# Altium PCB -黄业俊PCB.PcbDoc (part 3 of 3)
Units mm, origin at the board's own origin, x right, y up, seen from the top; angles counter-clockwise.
Board outline 130 x 100.6 mm, 2 copper layers (Top Layer, Bottom Layer); 47 components, 24 nets, 117 pads, 0 vias.
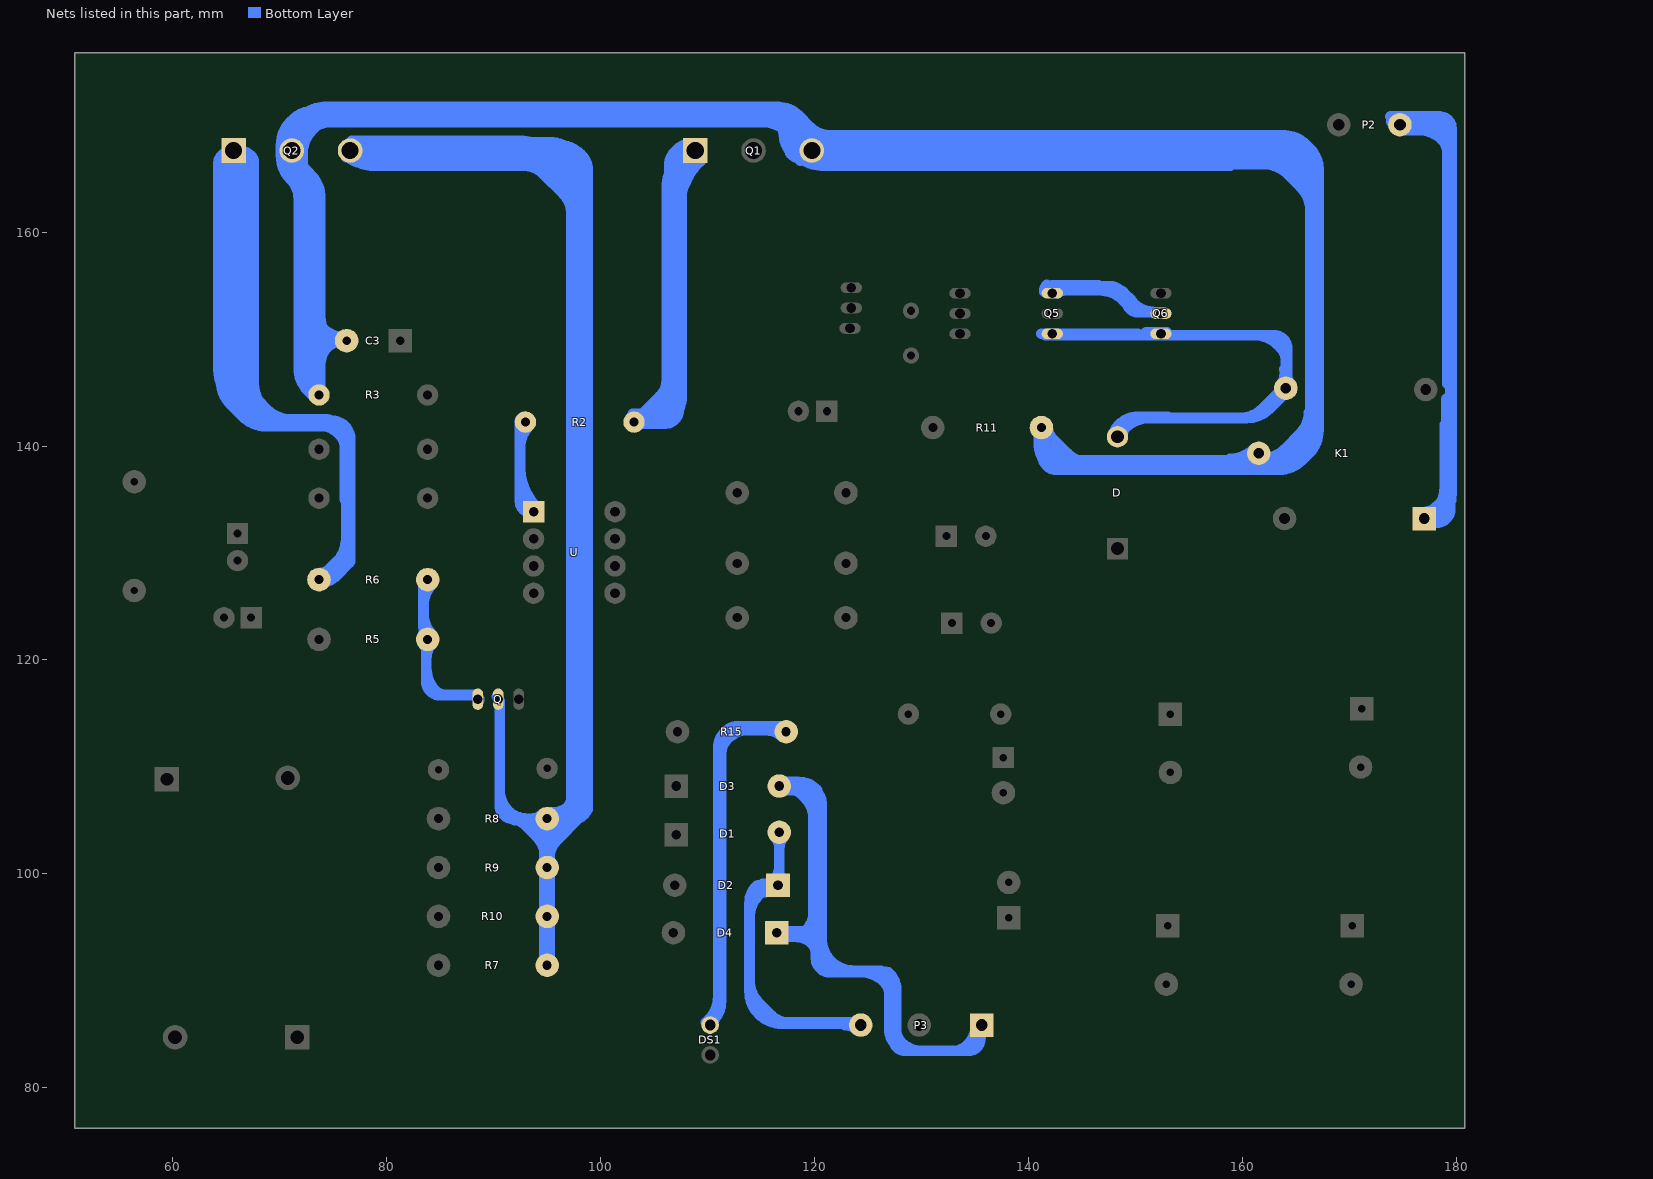
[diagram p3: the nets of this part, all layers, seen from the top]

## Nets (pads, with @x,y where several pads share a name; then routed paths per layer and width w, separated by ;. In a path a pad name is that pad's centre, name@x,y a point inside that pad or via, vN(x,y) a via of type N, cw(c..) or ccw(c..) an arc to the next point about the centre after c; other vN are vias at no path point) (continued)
NetD1_1: D1.1 D2.2 P3.3 | length 114.1
  Bottom Layer w1: 113.919,91.059 113.919,89.408 ccw(c116.985,89.408) 114.817,87.24 115.053,87.004 ccw(c117.221,89.172) 117.221,86.106 P3.3@123.698,86.106 ; 113.919,91.313 113.919,90.043 ccw(c116.985,90.043) 114.817,87.875 115.815,86.877 ccw(c117.983,89.045) 117.983,85.979 120.142,85.979 ; 113.919,94.107 113.919,95.885 cw(c116.985,95.885) 114.817,98.053 115.465,98.701 cw(c116.332,97.834) D2.2@116.332,99.06 ; 115.02,98.256 cw(c115.754,97.523) D2.2@116.281,98.416 ; 115.412,98.267 cw(c116.713,96.966) D2.2@116.713,98.806 ; D2.2@116.586,98.933 114.861,98.933 ccw(c114.861,98.499) 114.554,98.806 ccw(c116.087,97.273) 113.919,97.273 113.919,89.001 ccw(c116.923,89.001) 114.046,88.137 ccw(c116.923,89.001) 114.173,87.792 ccw(c116.923,89.001) 114.799,86.877 ccw(c116.967,89.045) 116.967,85.979 P3.3@124.587,85.979 ; D2.2@116.713,99.06 D1.1@116.713,103.886 ; 122.271,86.106 cw(c122.271,83.79) P3.3@123.909,85.428 ; 115.137,98.933 cw(c115.137,97.484) 116.162,98.509 ccw(c115.137,97.484) 115.137,98.933 ; 115.137,98.933 ccw(c115.137,100.382) D2.2@116.162,99.357 ; 115.137,98.933 ccw(c115.137,100.382) D2.2@116.162,99.357 ; 115.164,99.06 cw(c115.164,97.905) D2.2@116.1,98.582 ; 115.164,99.06 cw(c115.164,97.905) D2.2@116.1,98.582 ; 115.164,99.06 cw(c115.164,97.905) D2.2@116.1,98.582 ; 115.444,99.06 ccw(c115.444,100.075) D2.2@116.162,99.357 ; 115.444,99.06 ccw(c115.444,100.075) D2.2@116.162,99.357 ; 115.444,99.06 ccw(c115.444,100.075) D2.2@116.162,99.357 ; D2.2@116.162,99.357 ccw(c114.831,100.688) 116.713,100.688 ; D2.2@116.162,99.357 ccw(c114.831,100.688) 116.713,100.688 ; D2.2@116.162,99.357 ccw(c114.831,100.688) 116.713,100.688 ; D2.2@116.162,99.357 ccw(c114.831,100.688) 116.713,100.688 ; D2.2@116.162,99.357 ccw(c114.831,100.688) 116.713,100.688 ; D1.1@116.289,103.462 cw(c115.264,102.437) 116.713,102.437 ; D1.1@116.289,103.462 cw(c115.264,102.437) 116.713,102.437 ; D1.1@116.289,103.462 cw(c115.264,102.437) 116.713,102.437 ; D1.1@116.289,103.462 cw(c115.264,102.437) 116.713,102.437 ; D1.1@116.289,103.462 cw(c115.264,102.437) 116.713,102.437 ; 116.713,100.075 ccw(c117.728,100.075) D2.2@117.01,99.357 ; 116.713,100.075 ccw(c117.728,100.075) D2.2@117.01,99.357 ; 116.713,100.075 ccw(c117.728,100.075) D2.2@117.01,99.357 ; 116.713,100.075 ccw(c117.728,100.075) D2.2@117.01,99.357 ; 116.713,100.075 ccw(c117.728,100.075) D2.2@117.01,99.357 ; 116.713,102.437 cw(c118.162,102.437) D1.1@117.137,103.462 ; 116.713,102.437 cw(c118.162,102.437) D1.1@117.137,103.462 ; 116.713,102.437 cw(c118.162,102.437) D1.1@117.137,103.462 ; 116.713,102.437 cw(c118.162,102.437) D1.1@117.137,103.462 ; 116.713,102.437 cw(c118.162,102.437) D1.1@117.137,103.462 ; 122.578,85.979 cw(c122.578,84.097) P3.3@123.909,85.428 ; 122.578,85.979 cw(c122.578,84.097) P3.3@123.909,85.428 ; 122.578,85.979 cw(c122.578,84.097) P3.3@123.909,85.428 ; 122.578,85.979 cw(c122.578,84.097) P3.3@123.909,85.428 ; 122.578,85.979 cw(c122.578,84.097) P3.3@123.909,85.428 ; 122.884,85.852 ccw(c122.884,87.301) P3.3@123.909,86.276 ; 122.884,85.852 cw(c122.884,84.403) P3.3@123.909,85.428 ; 122.884,85.852 ccw(c122.884,87.301) P3.3@123.909,86.276 ; 122.884,85.852 cw(c122.884,84.403) P3.3@123.909,85.428 ; 122.884,85.852 ccw(c122.884,87.301) P3.3@123.909,86.276 ; 122.884,85.852 cw(c122.884,84.403) P3.3@123.909,85.428 ; 123.191,85.979 ccw(c123.191,86.994) P3.3@123.909,86.276 ; 123.191,85.979 ccw(c123.191,86.994) P3.3@123.909,86.276 ; 123.191,85.979 ccw(c123.191,86.994) P3.3@123.909,86.276 ; 123.191,85.979 ccw(c123.191,86.994) P3.3@123.909,86.276 ; 123.191,85.979 ccw(c123.191,86.994) P3.3@123.909,86.276
NetD3_1: D3.1 D4.2 P3.1 | length 235.5
  Bottom Layer w1: D4.2@116.205,94.615 118.999,94.615 cw(c118.999,93.345) 119.396,94.551 cw(c118.999,93.345) 120.142,93.899 ; D4.2@116.332,94.107 118.228,94.107 ; D3.1@116.713,108.331 118.662,108.331 cw(c118.662,106.597) 119.888,107.823 ; D4.2@116.84,94.488 ccw(c117.147,94.795) 117.147,94.361 118.526,94.361 ccw(c118.526,95.197) 119.117,94.606 ccw(c116.949,96.774) 120.015,96.774 120.015,106.767 ccw(c118.999,106.767) 119.717,107.486 ccw(c117.983,105.751) 117.983,108.204 cw(c117.983,109.43) 117.116,108.563 117.094,108.585 118.429,108.585 ; D4.2@116.968,94.806 ccw(c118.228,95.592) 118.228,94.107 ; D3.1@117.094,107.823 118.005,107.823 ; D3.1@117.23,107.9 cw(c118.429,107.193) 118.429,108.585 ; D3.1@117.291,108.365 ccw(c118.005,108.564) 118.005,107.823 ; 117.601,94.361 ccw(c117.601,93.346) 116.883,94.064 cw(c118.214,92.733) 118.214,94.615 ; 117.601,94.615 cw(c117.601,95.63) 116.883,94.912 ccw(c118.214,96.243) 118.214,94.361 ; 117.855,108.331 cw(c117.855,109.346) D3.1@117.137,108.628 ; 118.468,108.331 ccw(c118.468,106.449) D3.1@117.137,107.78 ; 119.126,108.458 cw(c119.126,107.538) 119.776,108.189 cw(c118.281,106.693) 120.396,106.693 120.396,93.586 ccw(c123.431,93.586) 121.285,91.44 ; 119.634,94.869 ccw(c119.021,95.482) 119.888,95.482 119.888,105.283 ccw(c117.435,105.283) 119.17,107.017 118.618,107.569 ccw(c118.005,106.956) 118.005,107.823 ; 120.142,92.71 ccw(c118.916,93.936) 120.65,93.936 120.65,106.649 ccw(c119.349,106.649) 120.269,107.569 ccw(c118.736,106.036) 118.736,108.204 D3.1@116.713,108.204 118.872,108.204 cw(c118.872,106.934) 120.142,106.934 120.142,93.899 ; 120.142,93.091 120.142,92.075 ccw(c121.412,92.075) 121.412,90.805 126.08,90.805 cw(c126.08,89.504) 127,90.424 cw(c126.08,89.504) 127.381,89.504 127.381,84.557 ccw(c128.499,84.557) 128.499,83.439 134.391,83.439 ccw(c134.391,84.557) 135.509,84.557 P3.1@135.509,85.852 ; 120.269,93.091 120.269,93.345 ccw(c118.999,93.345) 120.142,93.899 ; 120.65,94.488 120.65,93.98 ccw(c123.716,93.98) 121.548,91.812 ccw(c123.672,93.936) 123.672,90.932 125.222,90.932 ; 124.079,90.805 124.333,90.805 cw(c124.333,87.739) 126.501,89.907 cw(c125.296,88.702) 127,88.702 127,85.48 ccw(c129.168,85.48) 127.635,83.947 ccw(c128.861,85.173) 128.861,83.439 131.572,83.439 ; 127.889,84.201 cw(c128.502,84.814) 127.635,84.814 127.635,85.852 cw(c128.861,87.078) 127.127,87.078 127.127,89.281 ccw(c125.287,89.281) 126.588,90.582 126.365,90.805 ccw(c126.058,90.498) 126.058,90.932 123.032,90.932 cw(c123.032,93.998) 120.864,91.83 120.142,92.552 ccw(c118.841,92.552) 119.761,93.472 ccw(c118.228,91.939) 118.228,94.107 ; 134.434,84.142 ccw(c132.957,85.62) P3.1@135.038,85.8 ; P3.1@135.636,85.725 cw(c134.716,85.725) 135.367,85.075 134.18,83.888 cw(c133.096,84.972) 133.096,83.439 129.983,83.439 cw(c129.983,86.041) 128.143,84.201 cw(c129.369,85.427) 127.635,85.427 127.635,89.145 ccw(c125.467,89.145) 127,90.678 ccw(c126.693,90.371) 126.693,90.805 123.317,90.805 cw(c123.317,93.871) 121.149,91.703 cw(c123.273,93.827) 120.269,93.827 120.269,95.758 120.269,107.823 ccw(c118.429,105.983) 118.429,108.585 ; D3.1@117.137,107.78 cw(c118.162,106.755) 118.162,108.204 ; D3.1@117.137,107.78 cw(c118.162,106.755) 118.162,108.204 ; D3.1@117.137,107.78 cw(c118.162,106.755) 118.162,108.204 ; D3.1@117.137,107.78 cw(c118.162,106.755) 118.162,108.204 ; D3.1@117.137,107.78 cw(c118.162,106.755) 118.162,108.204 ; D3.1@117.137,107.78 cw(c118.162,106.755) 118.162,108.204 ; D3.1@117.137,108.628 ccw(c118.162,109.653) 118.162,108.204 ; D3.1@117.137,108.628 ccw(c118.162,109.653) 118.162,108.204 ; D3.1@117.137,108.628 ccw(c118.162,109.653) 118.162,108.204 ; D3.1@117.137,108.628 ccw(c118.162,109.653) 118.162,108.204 ; D3.1@117.137,108.628 ccw(c118.162,109.653) 118.162,108.204 ; D3.1@117.137,108.628 ccw(c118.162,109.653) 118.162,108.204 ; P3.1@135.212,85.428 cw(c134.494,84.71) 135.509,84.71 ; P3.1@135.212,85.428 cw(c134.494,84.71) 135.509,84.71 ; P3.1@135.212,85.428 cw(c134.494,84.71) 135.509,84.71 ; P3.1@135.212,85.428 cw(c134.494,84.71) 135.509,84.71 ; P3.1@135.212,85.428 cw(c134.494,84.71) 135.509,84.71 ; 135.509,84.55 cw(c136.438,84.55) P3.1@135.951,85.341 ; 135.509,84.55 cw(c136.438,84.55) P3.1@135.951,85.341 ; 135.509,84.55 cw(c136.438,84.55) P3.1@135.951,85.341 ; 135.509,84.55 cw(c136.438,84.55) P3.1@135.951,85.341 ; 135.509,84.55 cw(c136.438,84.55) P3.1@135.951,85.341
NetD_1: D.1 K1.5 Q5.3 Q6.3 | length 149.7
  Bottom Layer w1: 141.224,150.495 150.241,150.495 ; Q5.3@141.605,150.368 Q6.3@152.654,150.368 ; Q5.3@142.24,150.368 162.941,150.368 cw(c162.941,149.098) 164.211,149.098 K1.5@164.211,145.288 ; D.1@147.955,140.716 cw(c149.795,140.716) 148.494,142.017 cw(c150.259,140.252) 150.259,142.748 153.035,142.748 ccw(c153.342,143.055) 153.342,142.621 160.401,142.621 ; D.1@148.082,140.716 D.1@148.082,140.866 ; D.1@148.209,140.843 149.089,141.723 ; 151.003,150.622 Q6.3@152.933,150.622 ; Q6.3@152.146,150.368 Q6.3@152.146,150.495 ; 154.051,142.621 159.766,142.621 ccw(c159.766,145.687) 161.934,143.519 163.635,145.22 ccw(c162.551,146.304) K1.5@164.084,146.304 ; 157.226,150.368 161.163,150.368 cw(c161.163,147.302) 163.331,149.47 163.576,149.225 cw(c162.35,147.999) 164.084,147.999 K1.5@164.084,146.304 ; 160.528,150.368 161.557,150.368 cw(c161.557,147.333) 163.703,149.479 cw(c162.477,148.253) 164.211,148.253 164.211,147.955 ; 162.626,144.211 cw(c164.084,142.753) K1.5@164.084,144.815 ; 163.068,144.018 163.186,144.136 ccw(c161.018,146.304) K1.5@164.084,146.304 ; 163.259,144.209 ccw(c162.536,144.931) K1.5@163.511,145.236 ; 163.377,144.327 ccw(c162.838,144.865) K1.5@163.535,145.173 ; K1.5@163.712,145.886 ccw(c162.896,146.917) 164.211,146.917 ; K1.5@163.957,145.415 163.957,145.542 K1.5@164.084,145.542 ; 164.084,147.574 K1.5@164.084,146.304 ; 164.211,148.844 164.211,146.917 ; K1.5@164.338,145.288 162.569,143.519 cw(c160.401,145.687) 160.401,142.621 ; 149.089,141.723 ccw(c149.737,141.075) 148.831,140.94 cw(c149.737,141.075) 149.089,141.723 ; 149.089,141.723 cw(c151.257,139.555) 151.257,142.621 160.401,142.621 ; 160.401,142.621 ccw(c160.401,145.38) 162.352,143.429 163.059,144.136 ccw(c160.891,146.304) 163.957,146.304 ccw(c163.344,146.917) 164.211,146.917 ; K1.5@163.66,145.839 ccw(c162.329,147.17) 164.211,147.17 ; K1.5@163.66,145.839 ccw(c162.635,146.864) 164.084,146.864 ; K1.5@163.66,145.839 ccw(c162.635,146.864) 164.084,146.864 ; K1.5@163.66,145.839 ccw(c162.329,147.17) 164.211,147.17 ; K1.5@163.66,145.839 ccw(c162.942,146.557) 163.957,146.557 ; K1.5@163.66,145.839 ccw(c162.942,146.557) 163.957,146.557 ; K1.5@163.66,145.839 ccw(c162.942,146.557) 163.957,146.557 ; K1.5@163.66,145.839 ccw(c162.329,147.17) 164.211,147.17 ; 163.957,147.17 ccw(c165.839,147.17) K1.5@164.508,145.839 ; 163.957,147.17 ccw(c165.839,147.17) K1.5@164.508,145.839 ; 163.957,147.17 ccw(c165.839,147.17) K1.5@164.508,145.839 ; 164.084,146.864 ccw(c165.533,146.864) K1.5@164.508,145.839 ; 164.084,146.864 ccw(c165.533,146.864) K1.5@164.508,145.839 ; 164.211,146.557 ccw(c165.226,146.557) K1.5@164.508,145.839 ; 164.211,146.557 ccw(c165.226,146.557) K1.5@164.508,145.839 ; 164.211,146.557 ccw(c165.226,146.557) K1.5@164.508,145.839 ; 164.211,146.557 ccw(c165.226,146.557) K1.5@164.508,145.839 ; D.1@148.336,141.366 ccw(c148.336,142.322) 149.012,141.646 cw(c148.336,142.322) D.1@148.336,141.366 ; 162.79,143.74 ccw(c161.116,145.415) 163.484,145.415 cw(c161.116,145.415) 162.79,143.74
NetDS1_1: DS1.1 R15.1 | length 108.9
  Bottom Layer w1: DS1.1@109.855,86.106 110.1,86.351 ccw(c107.932,88.519) 110.998,88.519 110.998,91.895 cw(c111.432,91.895) 111.125,92.202 ; DS1.1@110.236,85.979 ccw(c108.396,87.819) 110.998,87.819 110.998,111.751 cw(c113.166,111.751) 111.633,113.284 cw(c112.859,112.058) 112.859,113.792 117.094,113.792 R15.1@117.221,113.792 ; DS1.1@110.49,86.233 ccw(c108.65,88.073) 111.252,88.073 111.252,110.389 ; 111.252,97.663 111.252,111.129 cw(c113.389,111.129) 111.878,112.64 cw(c114.046,110.472) 114.046,113.538 115.316,113.538 ; 111.252,110.236 111.252,111.435 cw(c112.956,111.435) 111.751,112.64 cw(c113.919,110.472) 113.919,113.538 R15.1@117.475,113.538 ; 111.252,110.871 111.252,112.141 cw(c112.522,112.141) 112.522,113.411 R15.1@117.602,113.411 ; 112.395,113.03 112.395,113.157 ; 114.673,113.792 cw(c114.673,110.609) R15.1@116.924,112.86 ; 115.286,113.538 cw(c115.286,111.222) R15.1@116.924,112.86 ; R15.1@116.924,112.86 ccw(c115.593,111.529) 115.593,113.411 cw(c115.593,111.529) R15.1@116.924,112.86 ; 116.206,113.411 ccw(c116.206,114.426) 116.924,113.708 cw(c116.206,114.426) 116.206,113.411
NetK1_1: K1.1 P2.1 | length 195.6
  Bottom Layer w1: 173.863,170.815 178.46,170.815 ; P2.1@173.99,170.815 173.99,170.592 ccw(c175.291,170.592) 174.371,169.672 ccw(c174.678,169.979) 174.678,169.545 176.543,169.545 ; P2.1@174.244,170.053 176.797,170.053 cw(c176.797,167.018) 178.943,169.164 cw(c177.717,167.938) 179.451,167.938 179.451,134.112 cw(c178.181,134.112) 178.181,132.842 ; P2.1@174.244,170.307 177.664,170.307 cw(c177.664,168.139) 179.197,169.672 179.324,169.545 ; P2.1@174.469,170.336 cw(c175.626,169.179) 175.626,170.815 ; P2.1@174.668,170.477 ccw(c175.693,171.502) 175.693,170.053 ccw(c175.693,168.604) P2.1@174.668,169.629 ; P2.1@175.176,170.477 ccw(c176.201,171.502) 176.201,170.053 ccw(c176.201,168.604) P2.1@175.176,169.629 ; P2.1@175.289,170.321 ccw(c176.543,170.946) 176.543,169.545 ; 176.306,170.307 ccw(c176.306,167.991) P2.1@174.668,169.629 ; 176.814,170.307 ccw(c176.814,167.991) P2.1@175.176,169.629 ; K1.1@176.911,132.842 177.475,132.842 ccw(c177.475,134.546) 178.68,133.341 ccw(c176.512,135.509) 179.578,135.509 179.578,162.56 ; K1.1@176.911,133.096 178.711,134.896 ccw(c177.844,135.763) 179.07,135.763 179.07,144.404 ; K1.1@176.911,133.223 176.924,133.223 ccw(c176.924,136.258) 179.07,134.112 ccw(c178.15,135.032) 179.451,135.032 179.451,139.065 ; K1.1@177.038,133.823 ccw(c177.038,135.272) 178.062,134.247 ccw(c179.087,133.223) K1.1@177.638,133.223 ; K1.1@177.165,132.842 178.181,132.842 ; K1.1@177.235,133.79 ccw(c177.491,134.53) K1.1@178.045,133.976 ; K1.1@177.419,133.35 K1.1@178.045,133.976 ; 178.04,170.815 ccw(c178.04,166.765) P2.1@175.176,169.629 ; 179.197,145.818 179.197,167.43 ccw(c177.463,167.43) 178.689,168.656 ccw(c176.543,166.51) 176.543,169.545 ; 179.451,143.002 cw(c178.225,143.002) 179.092,142.135 178.943,141.986 178.943,136.144 cw(c175.877,136.144) K1.1@178.045,133.976 ; 179.578,161.671 179.578,169.697 ; P2.1@173.961,170.336 cw(c175.118,169.179) P2.1@175.118,170.815 ; P2.1@173.961,170.336 cw(c175.118,169.179) P2.1@175.118,170.815 ; P2.1@173.961,170.336 cw(c175.118,169.179) P2.1@175.118,170.815 ; P2.1@173.961,170.336 cw(c175.118,169.179) P2.1@175.118,170.815 ; P2.1@174.668,169.629 cw(c177.532,166.765) 177.532,170.815 ; P2.1@174.668,169.629 cw(c177.532,166.765) 177.532,170.815 ; P2.1@174.668,169.629 cw(c177.532,166.765) 177.532,170.815 ; P2.1@174.668,169.629 cw(c177.532,166.765) 177.532,170.815 ; K1.1@177.631,133.314 ccw(c178.181,133.398) 178.181,132.842 ; K1.1@177.631,133.314 ccw(c178.181,133.398) 178.181,132.842 ; K1.1@177.631,133.314 ccw(c178.181,133.398) 178.181,132.842 ; K1.1@177.631,133.314 ccw(c178.181,133.398) 178.181,132.842 ; K1.1@177.631,133.314 ccw(c178.181,133.398) 178.181,132.842 ; 178.46,170.815 cw(c178.46,169.697) 179.578,169.697 ; 178.46,170.815 cw(c178.46,169.697) 179.578,169.697 ; 178.46,170.815 cw(c178.46,169.697) 179.578,169.697
NetQ1_1: Q1.1 R2.2 | length 193.5
  Bottom Layer w1: R2.2@102.743,142.113 106.045,142.113 ccw(c106.045,143.383) 107.315,143.383 107.315,167.259 ; R2.2@102.87,142.748 ccw(c102.87,145.201) 104.604,143.466 105.382,144.244 ccw(c103.474,146.152) 106.172,146.152 106.172,149.352 ; R2.2@102.997,143.002 103.632,143.002 ccw(c103.632,146.068) 105.8,143.9 ccw(c104.902,144.798) 106.172,144.798 106.172,164.211 cw(c109.238,164.211) 107.07,166.379 ; R2.2@103.124,142.74 ccw(c103.124,143.947) 103.978,143.094 ccw(c104.831,142.24) R2.2@103.624,142.24 ; R2.2@103.251,142.367 104.144,142.367 ; R2.2@103.378,142.494 105.528,144.644 ccw(c103.36,146.812) 106.426,146.812 106.426,151.003 ; R2.2@103.57,142.014 cw(c104.144,141.724) 104.144,142.367 ; 107.188,167.005 107.188,158.877 107.188,144.649 cw(c105.051,144.649) 106.562,143.138 cw(c104.394,145.306) 104.394,142.24 103.251,142.24 105.581,142.24 ccw(c105.581,143.974) 106.807,142.748 ccw(c104.967,144.588) 107.569,144.588 107.569,164.719 cw(c110.635,164.719) 108.467,166.887 Q1.1@108.839,167.259 ; 107.315,161.857 cw(c114.125,161.857) Q1.1@109.31,166.672 ; 107.315,164.271 cw(c111.711,164.271) Q1.1@108.603,167.379 ; 107.315,166.37 107.315,167.355 ccw(c106.776,167.355) 107.157,167.736 cw(c108.458,166.435) 108.458,168.275 cw(c108.458,167.968) 108.675,168.185 109.22,167.64 cw(c108.913,167.333) 109.347,167.333 Q1.1@109.347,166.624 ; 107.569,167.049 cw(c109.303,167.049) Q1.1@108.077,168.275 ; Q1.1@108.234,166.925 ccw(c107.241,166.593) 107.241,167.64 ; Q1.1@109.347,167.64 107.241,167.64 ; R2.2@103.478,142.594 ccw(c104.331,143.447) 104.331,142.24 ; R2.2@103.478,142.594 ccw(c104.331,143.447) 104.331,142.24 ; R2.2@103.478,142.594 ccw(c104.638,143.754) 104.638,142.113 ; R2.2@103.478,142.594 ccw(c104.638,143.754) 104.638,142.113 ; R2.2@103.478,142.594 ccw(c104.638,143.754) 104.638,142.113 ; R2.2@103.478,142.594 ccw(c104.638,143.754) 104.638,142.113 ; R2.2@103.478,142.594 ccw(c104.638,143.754) 104.638,142.113 ; 104.144,142.367 ccw(c104.144,144.504) 105.655,142.993 ccw(c103.487,145.161) 106.553,145.161 106.553,146.759 ccw(c106.119,146.759) 106.426,147.066 106.426,166.287 cw(c108.16,166.287) 106.934,167.513 cw(c107.241,167.206) 107.241,167.64 ; 104.331,142.24 ccw(c104.331,141.033) 103.478,141.886 cw(c104.331,141.033) 104.331,142.24 ; 106.866,166.672 cw(c105.783,165.589) 107.315,165.589 ccw(c105.783,165.589) 106.866,166.672 ; 107.315,165.536 cw(c108.922,165.536) 107.786,166.672 ccw(c108.922,165.536) 107.315,165.536
NetQ2_1: Q2.1 R6.2 | length 319.1
  Bottom Layer w1: 64.262,150.929 64.262,166.488 cw(c65.204,166.488) 64.538,167.154 cw(c65.405,166.287) Q2.1@65.405,167.513 ; 64.262,152.781 64.262,147.066 ccw(c67.328,147.066) 65.16,144.898 67.31,142.748 ; 64.262,162.164 cw(c70.638,162.164) 66.13,166.672 ccw(c68.492,164.31) 65.151,164.31 ; 64.262,164.578 cw(c68.224,164.578) Q2.1@65.422,167.379 ; 64.516,151.384 64.516,146.05 ccw(c67.582,146.05) 65.414,143.882 66.539,142.757 ccw(c68.707,144.925) 68.707,141.859 74.041,141.859 ; Q2.1@65.151,166.624 65.151,145.796 ccw(c68.217,145.796) 66.049,143.628 66.412,143.265 ccw(c68.58,145.433) 68.58,142.367 74.847,142.367 cw(c74.847,140.633) 76.073,141.859 cw(c74.847,140.633) 76.581,140.633 76.581,129.339 cw(c76.147,129.339) 76.454,129.032 75.305,127.883 cw(c73.787,129.4) R6.2@73.787,127.254 ; Q2.1@65.278,167.259 ccw(c65.585,167.566) 65.585,167.132 66.294,167.132 66.57,167.132 cw(c66.57,166.265) 67.183,166.878 cw(c66.876,166.571) 67.31,166.571 67.31,145.297 ccw(c69.478,145.297) 67.945,143.764 68.407,143.302 ccw(c70.358,145.253) 70.358,142.494 71.374,142.494 ; Q2.1@65.659,167.64 66.084,167.64 cw(c66.084,165.906) 67.31,167.132 cw(c66.697,166.519) 67.564,166.519 67.564,145.796 ccw(c70.63,145.796) 68.462,143.628 69.079,143.011 ccw(c71.247,145.179) 71.247,142.113 71.501,142.113 ; 65.913,146.304 ccw(c68.979,146.304) 66.811,144.136 68.063,142.884 ccw(c70.231,145.052) 70.231,141.986 73.406,141.986 ; 66.548,163.443 ccw(c61.981,163.443) Q2.1@65.21,166.672 ; 66.548,165.857 ccw(c64.395,165.857) 65.917,167.379 cw(c62.556,164.018) 67.31,164.018 ; 66.548,166.116 66.548,145.087 ccw(c66.982,145.087) 66.675,144.78 ; 67.056,150.876 67.056,146.431 ccw(c70.122,146.431) 67.954,144.263 68.825,143.392 ccw(c70.993,145.56) 70.993,142.494 74.159,142.494 cw(c74.159,140.326) 75.692,141.859 75.983,141.568 cw(c75.766,141.351) 76.073,141.351 76.073,140.97 ; 67.183,153.543 67.183,146.177 ccw(c70.249,146.177) 68.081,144.009 68.825,143.265 ccw(c70.993,145.433) 70.993,142.367 73.546,142.367 cw(c73.546,139.332) 75.692,141.478 ; 67.31,161.603 ccw(c60.141,161.603) Q2.1@65.21,166.672 ; 71.882,141.986 73.406,141.986 ; R6.2@73.66,127.508 75.302,129.15 ccw(c73.134,131.318) 76.2,131.318 76.2,136.271 ; R6.2@73.66,128.108 ccw(c73.66,129.557) 74.684,128.532 ccw(c75.709,127.508) R6.2@74.26,127.508 ; 75.311,141.605 cw(c73.471,139.765) 76.073,139.765 ; 76.073,135.001 76.073,140.868 ccw(c74.955,140.868) 75.946,141.386 ccw(c74.955,140.868) 74.955,141.986 69.342,141.986 cw(c69.342,145.052) 67.174,142.884 66.802,143.256 cw(c68.948,145.402) 65.913,145.402 Q2.1@65.913,167.132 ; 76.073,137.16 76.073,139.883 ccw(c74.369,139.883) 75.574,141.088 ccw(c73.406,138.92) 73.406,141.986 ; Q2.1@65.21,166.672 cw(c63.514,164.976) 65.913,164.976 ; Q2.1@65.21,166.672 cw(c63.514,164.976) 65.913,164.976 ; Q2.1@65.21,166.672 cw(c63.514,164.976) 65.913,164.976 ; Q2.1@65.21,166.672 cw(c63.514,164.976) 65.913,164.976 ; Q2.1@65.21,166.672 cw(c63.514,164.976) 65.913,164.976 ; Q2.1@65.405,167.64 cw(c65.405,167.132) Q2.1@65.913,167.132 ; Q2.1@65.405,167.64 cw(c65.405,167.132) Q2.1@65.913,167.132 ; Q2.1@65.405,167.64 cw(c65.405,167.132) Q2.1@65.913,167.132
NetQ2_3: Q2.3 Q.2 R7.2 R8.2 R9.2 R10.2 | length 719.6
  Bottom Layer w1: Q2.3@76.073,167.64 cw(c77.606,166.107) 77.606,168.275 94.33,168.275 cw(c94.33,166.974) 95.25,167.894 ; Q2.3@76.2,167.005 76.2,167.303 cw(c77.934,167.303) 76.708,168.529 92.71,168.529 cw(c92.71,165.463) 94.878,167.631 96.012,166.497 ; Q2.3@76.2,167.132 94.869,167.132 cw(c94.869,164.066) 97.037,166.234 97.908,165.363 cw(c95.74,163.195) 98.806,163.195 98.806,106.045 ; Q2.3@76.454,167.005 ccw(c77.68,168.231) 77.68,166.497 92.583,166.497 cw(c92.583,163.431) 94.751,165.599 97.236,163.114 cw(c95.285,161.163) 98.044,161.163 98.044,106.86 cw(c97.61,106.86) 97.917,106.553 97.291,105.927 cw(c95.123,108.095) 95.123,105.029 93.853,105.029 ccw(c93.853,105.691) R8.2@94.453,105.41 ; Q2.3@76.454,167.132 ccw(c75.841,167.745) 76.708,167.745 cw(c78.294,166.16) 78.294,168.402 95.25,168.402 cw(c95.25,165.336) 97.418,167.504 98.171,166.751 ; Q2.3@76.581,168.148 96.012,168.148 cw(c96.012,165.082) 98.18,167.25 cw(c96.669,165.739) 98.806,165.739 98.806,161.925 ; Q2.3@76.708,167.005 93.643,167.005 cw(c93.643,165.271) 94.869,166.497 ; Q2.3@76.708,167.386 cw(c78.241,165.853) 78.241,168.021 93.673,168.021 cw(c93.673,167.587) 93.98,167.894 ; Q2.3@76.962,166.878 ccw(c78.495,168.411) 78.495,166.243 92.735,166.243 cw(c92.735,163.545) 94.643,165.453 96.492,163.604 cw(c94.584,161.696) 97.282,161.696 97.282,106.277 cw(c96.415,106.277) 97.028,105.664 ; 77.833,167.005 ccw(c77.833,165.869) Q2.3@77.03,166.672 ; 77.833,167.259 cw(c77.833,168.395) Q2.3@77.03,167.592 ; 78.178,168.148 ccw(c78.178,165.524) Q2.3@76.322,167.379 ; 78.446,167.005 cw(c78.446,169.008) Q2.3@77.03,167.592 ; 78.446,167.259 ccw(c78.446,165.256) Q2.3@77.03,166.672 ; 78.484,168.275 ccw(c78.484,165.218) Q2.3@76.322,167.379 ; 79.098,168.529 ccw(c79.098,164.604) Q2.3@76.322,167.379 ; 79.672,166.497 cw(c79.672,170.234) Q2.3@77.03,167.592 ; 80.592,168.148 ccw(c80.592,163.11) Q2.3@77.03,166.672 ; 80.899,168.275 ccw(c80.899,162.803) Q2.3@77.03,166.672 ; 81.512,168.529 ccw(c81.512,162.19) Q2.3@77.03,166.672 ; 89.281,166.243 93.091,166.243 cw(c93.091,163.177) 95.259,165.345 96.638,163.966 cw(c94.47,161.798) 97.536,161.798 97.536,157.988 ; Q.2@90.424,116.205 cw(c90.424,116.078) 90.551,116.078 90.551,106.426 ccw(c91.821,106.426) 91.821,105.156 97.536,105.156 ccw(c97.536,106.426) 98.806,106.426 ; 90.551,107.823 ccw(c93.31,107.823) 91.359,105.872 ccw(c93.087,107.6) 93.087,105.156 R8.2@95.25,105.156 ; 90.932,166.37 93.091,166.37 ; 93.091,167.132 cw(c93.091,164.066) 95.259,166.234 97.781,163.712 cw(c95.613,161.544) 98.679,161.544 98.679,107.057 ; 93.854,105.029 cw(c93.854,104.014) R8.2@94.572,104.732 ; 94.234,167.132 cw(c94.234,164.066) 96.402,166.234 98.298,164.338 cw(c97.072,163.112) 98.806,163.112 ; 94.234,167.64 95.504,167.64 cw(c95.504,164.574) 97.672,166.742 98.552,165.862 ; R7.2@94.572,91.864 ccw(c92.934,93.502) 95.25,93.502 ; R10.2@94.572,95.588 cw(c92.934,93.95) 95.25,93.95 ; R9.2@94.597,101.032 ccw(c93.298,102.489) 95.25,102.489 ; R8.2@94.615,104.902 ccw(c94.615,107.355) 96.349,105.62 ; 94.742,93.502 ccw(c97.058,93.502) R7.2@95.42,91.864 ; 94.742,93.95 cw(c97.058,93.95) R10.2@95.42,95.588 ; 94.742,98.074 ccw(c97.058,98.074) 95.42,96.436 cw(c96.751,97.767) 94.869,97.767 ; 94.742,98.522 cw(c97.058,98.522) 95.42,100.16 ccw(c96.751,98.829) 94.869,98.829 ; 94.742,102.646 ccw(c97.058,102.646) R9.2@95.42,101.008 ; 94.742,103.094 cw(c97.058,103.094) 95.42,104.732 cw(c96.445,103.707) 96.445,105.156 cw(c96.445,106.605) R8.2@95.42,105.58 ; R8.2@94.784,104.817 ccw(c95.582,106.094) 96.647,105.029 ; R7.2@94.869,91.059 cw(c94.869,91.186) 94.742,91.186 94.742,104.902 cw(c94.996,104.902) R8.2@94.996,105.156 ; R10.2@94.869,97.028 94.869,101.346 ccw(c91.803,101.346) 93.971,103.514 92.815,104.67 ccw(c91.948,103.803) 91.948,105.029 92.329,105.029 cw(c92.329,101.963) 94.497,104.131 cw(c93.599,103.233) 94.869,103.233 94.869,102.235 94.869,102.489 cw(c97.935,102.489) 95.767,104.657 cw(c97.278,103.146) 97.278,105.283 ccw(c97.278,106.518) 98.152,105.645 ccw(c96.879,106.917) 98.679,106.917 98.679,108.966 ; 94.869,97.154 cw(c93.854,97.154) 94.572,96.436 ccw(c92.934,98.074) 95.25,98.074 ; 94.869,99.442 ccw(c93.854,99.442) 94.572,100.16 cw(c92.934,98.522) 95.25,98.522 ; R8.2@95.09,105.749 ccw(c95.462,108.101) 97.146,106.417 ; R7.2@95.123,91.694 ccw(c94.816,92.001) 95.25,92.001 95.25,102.489 ; R9.2@95.123,100.711 95.123,101.092 cw(c98.189,101.092) 96.021,103.26 97.908,105.147 ccw(c95.74,107.315) 98.806,107.315 98.806,114.554 ; R8.2@95.268,105.691 ccw(c95.803,106.744) 96.638,105.909 ; R8.2@95.314,105.665 ccw(c96.266,107.188) 97.536,105.918 96.058,104.44 ccw(c98.009,102.489) 95.25,102.489 ; R8.2@95.401,105.599 ccw(c95.864,106.106) 96.349,105.62 ; R8.2@95.631,104.902 96.638,105.909 ; 97.908,164.728 cw(c95.74,162.56) 98.806,162.56 ; 97.917,161.544 ccw(c94.851,161.544) 97.019,163.712 95.259,165.472 ccw(c93.091,163.304) 93.091,166.37 ; 98.044,111.633 98.044,108.585 cw(c94.978,108.585) 97.146,106.417 ; 98.679,116.66 cw(c99.113,116.66) 98.806,116.967 ; Q2.3@77.03,166.672 cw(c78.139,165.563) 78.139,167.132 ; Q2.3@77.03,166.672 cw(c78.139,165.563) 78.139,167.132 ; Q2.3@77.03,166.672 cw(c78.139,165.563) 78.139,167.132 ; Q2.3@77.03,166.672 cw(c78.139,165.563) 78.139,167.132 ; Q2.3@77.03,167.592 ccw(c78.139,168.701) 78.139,167.132 ; Q2.3@77.03,167.592 ccw(c78.139,168.701) 78.139,167.132 ; Q2.3@77.03,167.592 ccw(c78.139,168.701) 78.139,167.132 ; Q2.3@77.03,167.592 ccw(c78.139,168.701) 78.139,167.132 ; Q.2@90.297,116.586 cw(c90.297,116.459) Q.2@90.424,116.459 ; Q.2@90.297,116.586 cw(c90.297,116.459) Q.2@90.424,116.459 ; Q.2@90.297,116.586 cw(c90.297,116.459) Q.2@90.424,116.459 ; 93.091,166.37 93.345,166.37 cw(c93.345,163.304) 95.513,165.472 96.638,164.347 cw(c94.47,162.179) 97.536,162.179 97.536,108.077 cw(c94.47,108.077) 96.638,105.909 ; 93.547,105.156 cw(c93.547,103.707) R8.2@94.572,104.732 ; 93.547,105.156 ccw(c93.547,106.605) 94.572,105.58 cw(c93.547,106.605) 93.547,105.156 ; 93.547,105.156 cw(c93.547,103.707) R8.2@94.572,104.732 ; 96.349,105.62 97.146,106.417
NetQ5_1: Q5.1 Q6.2 | length 71.7
  Bottom Layer w1: Q5.1@141.478,154.432 141.478,154.454 cw(c142.345,154.454) 141.732,155.067 ccw(c142.039,155.374) 142.039,154.94 147.723,154.94 cw(c147.723,154.073) 148.336,154.686 ccw(c148.949,154.686) 148.516,154.252 148.971,153.797 ; Q5.1@141.859,154.432 cw(c142.779,153.512) 142.779,154.813 147.745,154.813 cw(c147.745,153.079) 148.971,154.305 149.591,153.685 cw(c148.94,153.035) 149.86,153.035 ; Q5.1@141.859,154.686 143.913,154.686 ccw(c143.913,155.553) 144.526,154.94 ; Q5.1@141.986,154.432 ccw(c141.373,155.045) 142.24,155.045 146.431,155.045 cw(c146.431,154.686) 146.685,154.94 ; Q5.1@141.986,154.559 146.939,154.559 cw(c146.939,151.493) 149.107,153.661 149.262,153.506 cw(c149.045,153.289) 149.352,153.289 ccw(c149.659,153.289) 149.442,153.072 ; Q5.1@142.24,154.559 148.209,154.559 cw(c148.209,153.543) 148.755,154.4 cw(c148.209,153.543) 149.225,153.543 ccw(c150.241,153.543) 150.241,152.527 152.654,152.527 Q6.2@151.892,152.527 ; 143.66,154.686 ccw(c143.66,153.385) Q5.1@142.74,154.305 ; 143.966,154.813 ccw(c143.966,153.079) Q5.1@142.74,154.305 ; 144.018,154.559 146.685,154.559 cw(c146.685,151.493) 148.853,153.661 149.089,153.425 ccw(c151.257,155.593) 151.257,152.527 Q6.2@151.892,152.527 ; 144.273,154.94 ccw(c144.273,152.772) Q5.1@142.74,154.305 ; 144.527,155.045 ccw(c144.527,152.518) Q5.1@142.74,154.305 ; 145.161,154.686 147.193,154.686 cw(c147.193,151.62) 149.361,153.788 149.724,153.425 ccw(c151.892,155.593) Q6.2@151.892,152.527 ; Q5.1@142.74,154.305 cw(c143.353,153.692) 143.353,154.559 ; Q5.1@142.74,154.305 cw(c143.353,153.692) 143.353,154.559 ; Q5.1@142.74,154.305 cw(c143.353,153.692) 143.353,154.559 ; Q5.1@142.74,154.305 cw(c143.353,153.692) 143.353,154.559 ; Q5.1@142.74,154.305 cw(c143.353,153.692) 143.353,154.559 ; Q5.1@142.74,154.305 cw(c143.353,153.692) 143.353,154.559
NetQ_3: Q.1 R5.2 R6.1 | length 29.7
  Bottom Layer w1: R5.2@83.396,121.496 cw(c82.678,120.778) 83.693,120.778 ; 83.439,124.288 ccw(c86.188,124.288) R5.2@84.244,122.344 ; 83.439,125.14 cw(c86.188,125.14) R6.1@84.244,127.084 ; R6.1@83.439,127.508 83.439,123.072 ; 83.693,119.634 83.693,119.24 ccw(c86.728,119.24) 84.582,117.094 ccw(c85.502,118.014) 85.502,116.713 Q.1@88.265,116.713 ; 83.693,120.165 cw(c85.575,120.165) R5.2@84.244,121.496 ; R5.2@83.693,122.047 83.693,117.983 ccw(c84.963,117.983) 84.243,116.937 ccw(c84.963,117.983) 84.963,116.713 88.138,116.713 cw(c88.138,116.205) Q.1@88.646,116.205 ; R5.2@83.82,121.844 cw(c85.607,123.072) 83.439,123.072 ; R5.2@83.916,122.512 cw(c84.006,123.072) 83.439,123.072
NetR2_1: R2.1 U.1 | length 61.6
  Bottom Layer w1: U.1@93.726,133.858 U.1@93.726,134.366 ; U.1@93.98,133.731 U.1@93.574,133.731 ; 92.456,134.849 ccw(c93.574,134.849) U.1@93.574,133.731 ; 92.456,134.849 ccw(c93.574,134.849) U.1@93.574,133.731 ; 92.456,134.849 ccw(c93.574,134.849) U.1@93.574,133.731 ; 92.456,134.849 R2.1@92.456,142.24 ; 92.456,135.717 ccw(c95.585,135.717) U.1@93.372,133.504 ; 92.456,135.717 ccw(c95.585,135.717) U.1@93.372,133.504 ; 92.456,135.717 ccw(c95.585,135.717) U.1@93.372,133.504 ; 92.456,135.717 ccw(c95.585,135.717) U.1@93.372,133.504 ; 92.456,135.717 ccw(c95.585,135.717) U.1@93.372,133.504 ; 92.456,138.131 ccw(c97.999,138.131) U.1@94.08,134.212 ; 92.456,138.131 ccw(c97.999,138.131) U.1@94.08,134.212 ; 92.456,138.131 ccw(c97.999,138.131) U.1@94.08,134.212 ; 92.456,138.131 ccw(c97.999,138.131) U.1@94.08,134.212 ; 92.456,138.131 ccw(c97.999,138.131) U.1@94.08,134.212 ; 92.456,139.806 cw(c95.398,139.806) R2.1@93.318,141.886 ; 92.456,139.806 cw(c95.398,139.806) R2.1@93.318,141.886 ; 92.456,139.806 cw(c95.398,139.806) R2.1@93.318,141.886 ; 92.456,139.806 cw(c95.398,139.806) R2.1@93.318,141.886 ; 92.456,139.806 cw(c95.398,139.806) R2.1@93.318,141.886 ; R2.1@92.456,142.24 cw(c92.964,142.24) R2.1@92.964,142.748 ; R2.1@92.456,142.24 cw(c92.964,142.24) R2.1@92.964,142.748 ; R2.1@92.456,142.24 cw(c92.964,142.24) R2.1@92.964,142.748
OUT: C3.2 K1.3 Q1.3 Q2.2 R3.2 R11.2 | length 1503.5
  Bottom Layer w1: Q2.2@70.612,166.878 72.957,164.533 cw(c71.873,163.449) 73.406,163.449 73.406,145.647 ccw(c74.273,145.647) R3.2@73.66,145.034 ; Q2.2@70.866,167.132 70.866,167.894 cw(c73.932,167.894) 71.764,170.062 ; Q2.2@70.866,167.386 70.866,169.545 cw(c72.136,169.545) 71.12,170.307 cw(c72.136,169.545) 72.136,170.815 117.348,170.815 cw(c117.348,169.545) 118.618,169.545 ; Q2.2@70.993,166.878 70.993,167.513 cw(c74.059,167.513) 71.891,169.681 72.127,169.917 cw(c74.295,167.749) 74.295,170.815 76.073,170.815 ; Q2.2@71.12,167.005 71.12,170.254 cw(c71.554,170.254) 71.247,170.561 ; Q2.2@71.12,167.259 cw(c71.427,167.566) 70.993,167.566 70.993,167.845 cw(c73.564,167.845) 71.746,169.663 cw(c73.914,167.495) 73.914,170.561 115.316,170.561 cw(c115.316,167.495) 117.484,169.663 Q1.3@119.634,167.513 ; 71.247,169.926 72.235,170.914 cw(c74.143,169.006) 74.143,171.704 116.611,171.704 cw(c116.611,169.006) 118.519,170.914 119.606,169.827 ccw(c121.514,171.735) 121.514,169.037 163.982,169.037 cw(c163.982,166.339) 165.89,168.247 166.342,167.795 cw(c164.434,165.887) 167.132,165.887 167.132,156.464 ; Q2.2@71.76,167.02 ccw(c72.834,166.833) 72.063,166.062 ; Q2.2@71.768,167.085 ccw(c74.544,166.882) 72.576,164.914 ; Q2.2@71.769,167.164 cw(c74.734,167.31) 72.635,169.409 ; 72.013,166.112 ccw(c71.12,165.219) 71.12,166.482 ; 73.025,147.52 ccw(c76.4,147.52) 74.014,145.134 cw(c75.48,146.6) 73.406,146.6 ; 73.034,164.583 cw(c75.202,166.751) 72.136,166.751 72.136,167.386 cw(c75.202,167.386) 73.034,169.554 73.533,170.053 ; R3.2@73.406,144.78 cw(c75.552,146.926) 72.517,146.926 72.517,163.273 ccw(c69.64,163.273) 71.674,165.308 cw(c73.625,167.259) 70.866,167.259 72.127,165.998 cw(c69.959,163.83) 73.025,163.83 73.025,145.625 ccw(c74.759,145.625) R3.2@73.533,144.399 ; 73.533,154.178 73.533,152.217 ccw(c75.237,152.217) 74.032,151.012 ccw(c76.2,153.18) 76.2,150.114 C3.2@76.327,150.114 ; R3.2@73.66,144.526 cw(c73.66,145.446) 73.01,144.795 72.653,145.152 cw(c74.821,147.32) 71.755,147.32 71.755,163.146 ccw(c69.184,163.146) 71.002,164.964 cw(c73.17,167.132) 70.104,167.132 70.104,168.148 cw(c73.17,168.148) 71.002,170.316 71.247,170.561 ; R3.2@73.787,144.78 73.787,163.195 ccw(c70.721,163.195) 73.138,165.081 ccw(c70.721,163.195) 72.889,165.363 71.12,167.132 72.762,165.49 cw(c70.594,163.322) 73.66,163.322 73.66,160.962 ccw(c74.094,160.962) 73.787,160.655 ; R3.2@73.787,145.034 73.787,147.692 cw(c75.955,147.692) 74.422,149.225 cw(c75.648,147.999) 75.648,149.733 C3.2@75.819,149.733 ; 73.787,153.543 73.787,152.037 ccw(c76.59,152.037) 74.608,150.055 ccw(c75.692,151.139) C3.2@75.692,149.606 ; 73.914,149.86 75.46,149.86 ccw(c75.46,150.727) C3.2@76.073,150.114 ; 111.252,170.815 116.078,170.815 cw(c116.078,167.749) 118.246,169.917 cw(c117.655,169.326) 118.491,169.326 ccw(c121.027,169.326) 119.234,167.532 ccw(c119.893,168.192) 119.893,167.259 125.296,167.259 ; 112.141,170.561 114.935,170.561 cw(c114.935,167.495) 117.103,169.663 117.103,169.409 ccw(c120.169,169.409) 118.001,167.241 ccw(c118.571,167.811) 118.571,167.005 ; 114.3,170.942 115.189,170.942 cw(c115.189,167.876) 117.357,170.044 ccw(c120.423,170.044) 118.255,167.876 118.609,167.522 ccw(c120.777,169.69) 120.777,166.624 162.761,166.624 cw(c162.761,166.19) 163.068,166.497 cw(c163.068,164.044) 164.802,165.779 165.472,165.109 cw(c163.304,162.941) 166.37,162.941 166.37,140.081 165.236,138.947 cw(c163.068,141.115) 163.068,138.049 ; 116.078,170.688 118.228,168.538 ccw(c120.396,170.706) 120.396,167.64 164.763,167.64 cw(c164.763,165.906) 165.989,167.132 166.249,166.872 cw(c164.732,165.354) 166.878,165.354 ; 117.348,170.434 118.355,169.427 ccw(c120.523,171.595) 120.523,168.529 163.83,168.529 cw(c163.83,165.463) 165.998,167.631 ; 117.729,167.386 ccw(c119.262,168.919) 119.262,166.751 135.509,166.751 ; 117.856,168.783 ccw(c117.549,168.783) 117.766,169 117.357,169.409 ccw(c115.189,167.241) 115.189,170.307 74.803,170.307 ccw(c74.803,167.241) 72.635,169.409 ; 117.983,168.275 ccw(c119.516,168.275) 118.432,167.191 118.482,167.141 ccw(c120.65,169.309) 120.65,166.243 148.104,166.243 ccw(c148.104,167.11) 148.717,166.497 ; 118.453,168.694 cw(c116.891,167.132) Q1.3@119.1,167.132 ; 118.618,167.132 118.618,169.545 ; 118.618,168.191 ccw(c120.076,168.191) Q1.3@119.647,166.797 ; Q1.3@119.153,167.388 cw(c118.571,167.638) 118.571,167.005 ; Q1.3@119.22,166.756 ccw(c118.491,166.238) 118.491,167.132 ; Q1.3@119.22,167.508 cw(c118.491,168.026) 118.491,167.132 ; Q1.3@119.247,166.72 ccw(c118.11,165.79) 118.11,167.259 162.433,167.259 cw(c162.433,164.193) 164.601,166.361 166.234,164.728 cw(c164.066,162.56) 167.132,162.56 ; Q1.3@119.268,166.696 ccw(c118.571,166.064) 118.571,167.005 ; Q1.3@119.271,166.693 ccw(c117.983,165.511) 117.983,167.259 136.906,167.259 ; Q1.3@119.279,166.685 ccw(c118.237,165.696) 118.237,167.132 ; Q1.3@119.279,167.579 cw(c118.237,168.568) 118.237,167.132 ; Q1.3@119.503,166.885 ccw(c121.051,168.433) 121.051,166.243 ; Q1.3@119.503,167.379 cw(c122.278,164.604) 122.278,168.529 ; Q1.3@119.778,168.323 cw(c118.883,167.428) Q1.3@120.081,167.019 ; Q1.3@119.941,167.753 cw(c120.493,169.545) 118.618,169.545 ; 121.013,167.005 ccw(c121.013,165.869) Q1.3@120.21,166.672 ; 121.626,167.005 cw(c121.626,169.008) Q1.3@120.21,167.592 ; 122.239,166.751 cw(c122.239,169.621) Q1.3@120.21,167.592 ; 122.301,167.005 118.571,167.005 ; 122.546,166.624 cw(c122.546,169.928) Q1.3@120.21,167.592 ; 122.546,167.64 ccw(c122.546,164.336) Q1.3@120.21,166.672 ; 123.465,166.243 cw(c123.465,170.847) Q1.3@120.21,167.592 ; 124.46,166.878 162.687,166.878 ; 124.692,168.529 ccw(c124.692,162.19) Q1.3@120.21,166.672 ; 124.841,167.005 122.366,167.005 cw(c122.366,170.071) 120.198,167.903 119.253,168.848 ccw(c116.651,168.848) 118.491,170.688 ccw(c117.265,169.462) 117.265,171.196 116.078,171.196 ccw(c115.771,170.889) 115.771,171.323 73.087,171.323 ccw(c73.087,168.721) 71.247,170.561 ; R11.2@140.967,141.19 cw(c140.678,140.582) 141.351,140.582 ; 140.97,140.3 cw(c141.998,140.3) R11.2@141.509,141.204 ; R11.2@140.97,141.859 140.97,140.322 ccw(c144.005,140.322) 141.859,138.176 ccw(c142.472,138.789) 142.472,137.922 145.362,137.922 ccw(c145.362,138.356) 145.669,138.049 ; R11.2@141.224,141.132 cw(c141.224,139.683) 142.248,140.708 cw(c143.273,141.732) R11.2@141.824,141.732 ; R11.2@141.224,141.859 141.224,141.706 ccw(c144.228,141.706) 142.104,139.582 ccw(c144.272,141.75) 144.272,138.684 162.179,138.684 ccw(c162.179,141.75) 164.347,139.582 165.735,140.97 ccw(c163.589,143.116) 166.624,143.116 166.624,149.098 ; R11.2@141.224,142.113 ccw(c144.29,142.113) 142.122,139.945 142.612,139.455 ccw(c144.78,141.623) 144.78,138.557 146.304,138.557 ; R11.2@141.351,141.605 143.628,139.328 ccw(c145.796,141.496) 145.796,138.43 147.447,138.43 ; R11.2@141.351,141.986 141.351,139.424 ccw(c142.218,139.424) 141.605,138.811 ccw(c143.138,140.344) 143.138,138.176 162.687,138.176 ccw(c162.687,140.322) 164.205,138.805 166.234,140.834 ccw(c164.066,143.002) 167.132,143.002 167.132,165.989 ccw(c165.862,165.989) 165.862,167.259 118.364,167.259 ; 147.447,166.243 158.877,166.243 cw(c159.184,165.936) 159.184,166.37 162.052,166.37 cw(c162.052,163.304) 164.22,165.472 165.472,164.22 cw(c163.304,162.052) 166.37,162.052 166.37,159.385 ; 156.416,137.795 ccw(c156.416,144.447) K1.3@161.12,139.743 ; 156.591,167.132 165.862,167.132 cw(c165.862,165.862) 167.132,165.862 167.132,161.036 ; 157.336,138.176 ccw(c157.336,143.527) K1.3@161.12,139.743 ; 158.562,138.684 ccw(c158.562,142.301) K1.3@161.12,139.743 ; 158.83,137.795 ccw(c158.83,142.033) 161.827,139.036 cw(c159.75,141.113) 159.75,138.176 ; 160.528,167.132 162.179,167.132 cw(c162.179,164.066) 164.347,166.234 165.98,164.601 cw(c163.812,162.433) 166.878,162.433 166.878,141.942 cw(c165.144,141.942) 166.37,140.716 164.734,139.08 ccw(c165.385,138.43) 164.465,138.43 ; K1.3@161.036,139.7 cw(c161.036,139.065) K1.3@161.671,139.065 ; K1.3@161.119,139.742 cw(c158.877,141.974) 158.877,138.811 161.798,138.811 ccw(c161.798,141.877) 163.966,139.709 165.435,141.178 ccw(c163.484,143.129) 166.243,143.129 ccw(c165.323,144.049) 166.624,144.049 166.624,144.526 ; 161.29,167.259 118.364,167.259 ; K1.3@161.412,138.811 cw(c160.299,138.913) 160.299,137.795 142.621,137.795 cw(c142.621,139.065) 141.351,139.065 141.351,141.732 141.351,140.589 ccw(c144.417,140.589) 142.249,138.421 ccw(c143.76,139.932) 143.76,137.795 148.844,137.795 163.449,137.795 ccw(c163.449,140.861) 165.617,138.693 166.234,139.31 ccw(c164.066,141.478) 167.132,141.478 167.132,145.161 167.132,159.385 ; K1.3@161.544,139.573 161.544,137.922 ; 161.544,167.132 118.491,167.132 ; 161.925,137.922 163.195,137.922 ccw(c163.195,140.988) 165.363,138.82 166.234,139.691 ccw(c164.066,141.859) 167.132,141.859 167.132,161.29 ; 162.319,167.132 118.237,167.132 ; 164.973,167.132 166.624,165.481 ; 167.132,152.908 167.132,161.417 ; Q2.2@70.66,167.592 ccw(c69.551,168.701) 71.12,168.701 ccw(c72.689,168.701) Q2.2@71.58,167.592 ; Q2.2@70.66,167.592 ccw(c69.244,169.008) 71.247,169.008 cw(c69.244,169.008) Q2.2@70.66,167.592 ; 70.866,169.314 ccw(c73.302,169.314) Q2.2@71.58,167.592 ; 70.866,169.314 ccw(c73.302,169.314) Q2.2@71.58,167.592 ; 70.866,169.314 ccw(c73.302,169.314) Q2.2@71.58,167.592 ; Q2.2@70.993,167.005 cw(c70.993,166.878) Q2.2@71.12,166.878 ; Q2.2@70.993,167.005 cw(c70.993,166.878) Q2.2@71.12,166.878 ; Q2.2@70.993,167.005 cw(c70.993,166.878) Q2.2@71.12,166.878 ; Q2.2@70.993,167.005 cw(c72.833,167.005) 71.532,168.306 72.635,169.409 ; 71.12,166.482 cw(c71.12,164.913) 72.23,166.022 ; 71.12,166.482 cw(c71.12,164.913) 72.23,166.022 ; 71.12,166.482 cw(c71.12,164.913) 72.23,166.022 ; Q2.2@71.58,167.592 cw(c72.383,168.395) 71.247,168.395 ccw(c72.383,168.395) Q2.2@71.58,167.592 ; Q2.2@71.77,167.132 ccw(c73.339,167.132) 72.23,166.022 ; Q2.2@71.77,167.132 ccw(c73.339,167.132) 72.23,166.022 ; Q2.2@71.77,167.132 ccw(c73.339,167.132) 72.23,166.022 ; R3.2@73.306,145.134 ccw(c72.146,146.294) 73.787,146.294 ; R3.2@73.306,145.134 ccw(c72.146,146.294) 73.787,146.294 ; R3.2@73.306,145.134 ccw(c72.146,146.294) 73.787,146.294 ; 74.791,149.86 cw(c74.791,148.411) 75.816,149.436 ccw(c74.791,148.411) 74.791,149.86 ; 74.791,149.86 ccw(c74.791,151.309) 75.816,150.284 cw(c74.791,151.309) 74.791,149.86 ; 118.364,167.259 cw(c118.364,166.284) 119.196,166.793 ccw(c118.364,166.284) 118.364,167.259 ; 118.487,167.259 ccw(c118.487,168.395) Q1.3@119.29,167.592 ; 118.487,167.259 ccw(c118.487,168.395) Q1.3@119.29,167.592 ; 118.487,167.259 ccw(c118.487,168.395) Q1.3@119.29,167.592 ; 118.487,167.259 ccw(c118.487,168.395) Q1.3@119.29,167.592 ; 118.618,169.545 cw(c115.953,169.545) 117.78,167.605 ccw(c115.953,169.545) 118.618,169.545 ; Q1.3@120.21,166.672 cw(c121.626,165.256) 121.626,167.259 ; Q1.3@120.21,166.672 cw(c121.626,165.256) 121.626,167.259 ; Q1.3@120.21,166.672 cw(c121.626,165.256) 121.626,167.259 ; Q1.3@120.21,166.672 cw(c121.626,165.256) 121.626,167.259 ; Q1.3@120.21,166.672 cw(c121.626,165.256) 121.626,167.259 ; Q1.3@120.21,166.672 cw(c121.319,165.563) 121.319,167.132 ; Q1.3@120.21,166.672 cw(c121.319,165.563) 121.319,167.132 ; Q1.3@120.21,167.592 ccw(c121.013,168.395) 121.013,167.259 ; Q1.3@120.21,167.592 ccw(c121.013,168.395) 121.013,167.259 ; Q1.3@120.21,167.592 ccw(c121.013,168.395) 121.013,167.259 ; Q1.3@120.21,167.592 ccw(c121.013,168.395) 121.013,167.259 ; Q1.3@120.21,167.592 ccw(c121.013,168.395) 121.013,167.259 ; Q1.3@120.21,167.592 ccw(c121.319,168.701) 121.319,167.132 ; Q1.3@120.21,167.592 ccw(c121.319,168.701) 121.319,167.132 ; R11.2@140.8,141.308 cw(c139.469,139.977) 141.351,139.977 ; R11.2@140.8,141.308 cw(c139.469,139.977) 141.351,139.977 ; R11.2@140.8,141.308 cw(c139.775,140.283) 141.224,140.283 ; R11.2@140.8,141.308 cw(c139.775,140.283) 141.224,140.283 ; R11.2@140.8,141.308 cw(c139.775,140.283) 141.224,140.283 ; R11.2@140.8,141.308 cw(c139.469,139.977) 141.351,139.977 ; 141.224,140.283 cw(c142.673,140.283) R11.2@141.648,141.308 ; 141.224,140.283 cw(c142.673,140.283) R11.2@141.648,141.308 ; 141.224,140.283 cw(c142.673,140.283) R11.2@141.648,141.308 ; 141.351,140.59 cw(c142.366,140.59) R11.2@141.648,141.308 ; 141.351,140.59 cw(c142.366,140.59) R11.2@141.648,141.308 ; 141.351,140.59 cw(c142.366,140.59) R11.2@141.648,141.308 ; 141.351,140.59 cw(c142.366,140.59) R11.2@141.648,141.308 ; 161.544,137.922 cw(c162.87,137.922) 161.957,138.884 ccw(c162.87,137.922) 161.544,137.922 ; 161.544,137.922 ccw(c160.218,137.922) 161.131,138.884 cw(c160.218,137.922) 161.544,137.922 ; 118.686,166.672 cw(c120.102,165.256) 120.102,167.259 ccw(c120.102,165.256) 118.686,166.672 ; Q1.3@118.686,167.592 ccw(c119.489,168.395) 119.489,167.259 cw(c119.489,168.395) Q1.3@118.686,167.592
pads on no net: K1.2 U.5 U.6 U.7
copper on no net: | length 81.6
  Top Layer w0.3: 61.341,133.985 63.872,133.985 ccw(c63.872,136.153) 65.405,134.62 ; 64.008,121.92 70.051,121.92 cw(c70.051,121.486) 70.358,121.793 ; 76.962,146.812 78.858,146.812 cw(c78.858,144.644) 80.391,146.177 ; 77.47,154.178 79.134,154.178 cw(c79.134,151.143) 81.28,153.289 ; 78.105,120.396 81.661,120.396 ; 78.105,141.097 80.286,141.097 cw(c80.286,140.23) 80.899,140.843 ; 78.232,136.271 81.1,136.271 cw(c81.1,135.837) 81.407,136.144 ; 78.74,128.27 81.302,128.27 ccw(c81.302,129.137) 81.915,128.524 ; 86.36,102.108 92.837,102.108 ; 88.265,120.015 91.821,120.015 ; 95.631,133.223 99.358,133.223 cw(c99.358,131.489) 100.584,132.715 ; 95.631,143.129 98.819,143.129 cw(c98.819,140.094) 100.965,142.24 ; 115.697,137.922 117.93,137.922 ccw(c117.93,138.356) 118.237,138.049 ; 116.078,125.603 119.327,125.603 cw(c119.327,125.169) 119.634,125.476 ; 116.84,130.556 118.64,130.556 cw(c118.64,129.689) 119.253,130.302 ; 118.872,147.574 122.323,147.574 ; 122.428,157.099 125.603,157.099 ; 132.461,157.353 135.128,157.353 ; 132.842,144.78 136.293,144.78 cw(c136.293,143.913) 136.906,144.526 ; 140.716,157.099 144.018,157.099 ; 150.749,135.382 150.749,137.033 ; 151.638,155.702 154.432,155.702

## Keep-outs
Keep-Out Layer:
  the board outline again, w0.3

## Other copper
Bottom Layer:
  rectangle net GND: 137.287,98.679 152.4,108.204
  rectangle net GND: 52.959,77.343 63.373,115.062
  rectangle net GND: 149.733,95.25 179.959,110.998
  text "Deidre_141806048" at 131.191,172.339 h1.52
  text "2016-4-15" at 55.372,150.622 h1.52 r90

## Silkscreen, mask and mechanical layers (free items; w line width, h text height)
Top Overlay:
  circle w0.254: c65.93,84.709 r11.286
  circle w0.254: c64.787,108.712 r11.286
Drill Drawing:
  text ".LEGEND" at 185.88,81.28 h0.65
  text "Drill Drawing." at 185.88,78.74 h0.65

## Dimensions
50.8,76.2 to 50.8,176.8 on Mechanical 1
50.8,76.2 to 180.8,76.2 on Mechanical 1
